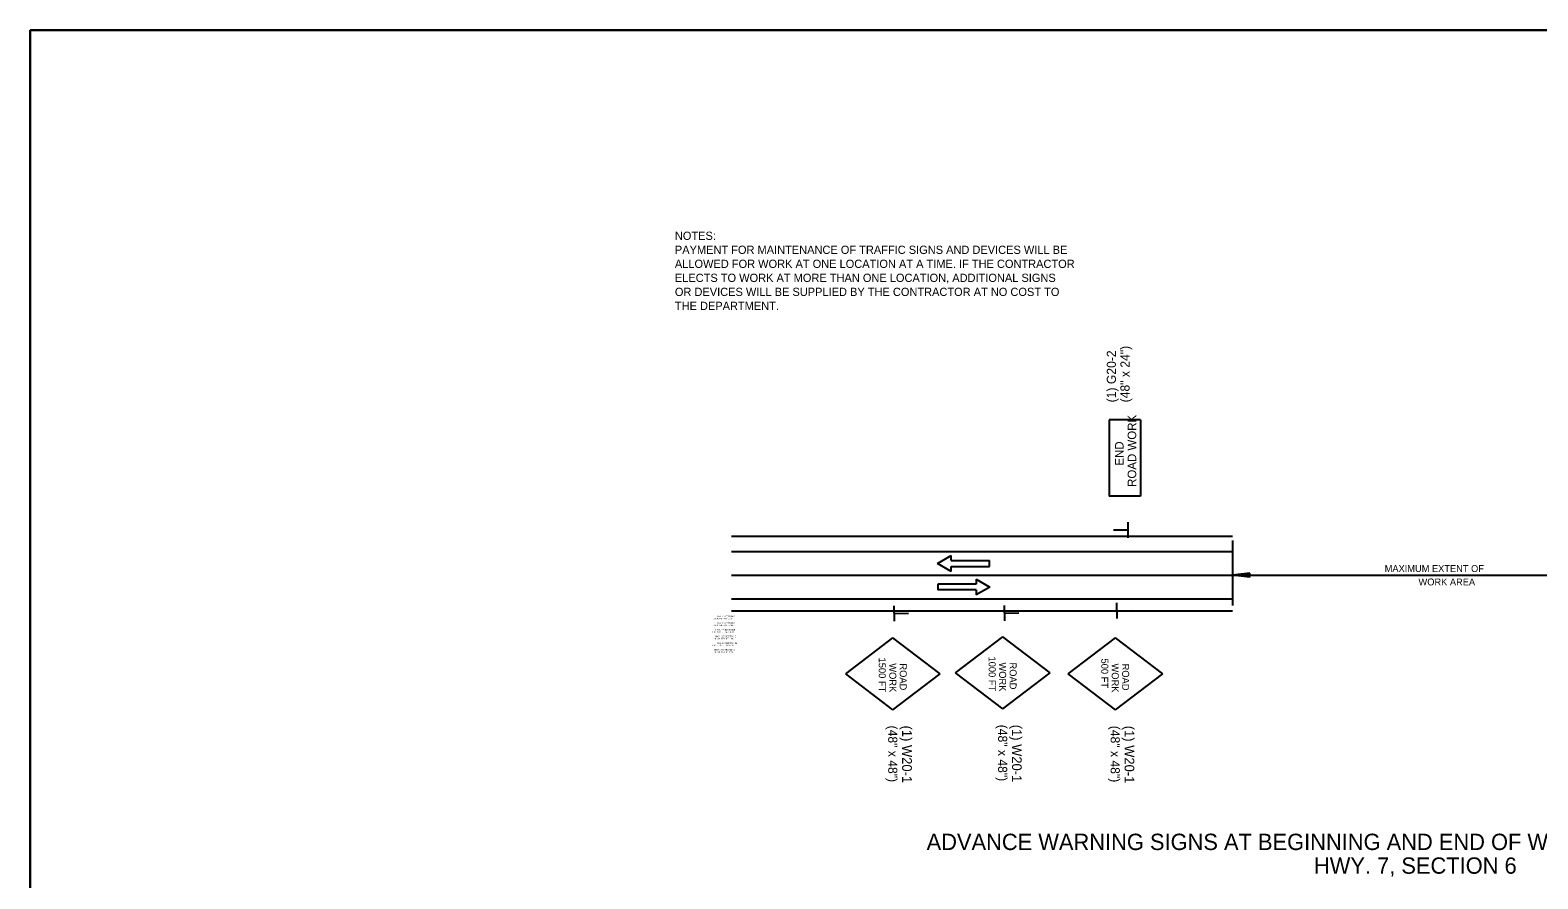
# Model space of a CAD drawing. Extents: x 1416408 to 1429341, y 372694 to 383211.
# Drawn here: x 1416408 to 1417967, y 376949 to 377826 of the extents above; entities that cross this region are included whole.
import ezdxf

# ---------------------------------------------------------------- set-up
doc = ezdxf.new("R2010")
doc.units = 0
for name, color, linetype in [('Default', 7, 'Continuous'), ('DSN_DRFT_Junk-No-Plot', 7, 'Continuous'), ('R_Border', 7, 'Continuous'), ('R_Draft', 7, 'Continuous'), ('R_Exist Surface', 7, 'Continuous'), ('R_MOT', 7, 'Continuous')]:
    doc.layers.add(name, color=color, linetype=linetype)

msp = doc.modelspace()

# ---------------------------------------------------------------- linework, layer by layer
at = {"layer": 'Default'}
for p, q in [((1417651, 377298.6), (1417651, 377231.7)), ((1417346, 377275), (1417359.9, 377283.1)), ((1417359.9, 377266.8), (1417346, 377275)), ((1417359.9, 377278), (1417359.9, 377283.1)), ((1417359.9, 377278), (1417399.5, 377278)), ((1417359.9, 377271.9), (1417399.5, 377271.9)), ((1417359.9, 377266.8), (1417359.9, 377271.9)), ((1417399.5, 377271.9), (1417399.5, 377278)), ((1417385.9, 377258.8), (1417385.9, 377253.7)), ((1417385.9, 377258.8), (1417399.8, 377250.6)), ((1417651, 377262.9), (1418113.3, 377262.9)), ((1417751.4, 377262.9), (1418012.8, 377262.9)), ((1417385.9, 377253.7), (1417346.3, 377253.7)), ((1417346.3, 377253.7), (1417346.3, 377247.6)), ((1417385.9, 377247.6), (1417346.3, 377247.6)), ((1417399.8, 377250.6), (1417385.9, 377242.5)), ((1417385.9, 377247.6), (1417385.9, 377242.5))]:
    msp.add_line(p, q, dxfattribs=at)
msp.add_lwpolyline([(1416407.7, 377826.5), (1416407.7, 376066.5), (1419127.7, 376066.5), (1419127.7, 377826.5)], close=True, dxfattribs=at)
at = {"layer": 'DSN_DRFT_Junk-No-Plot'}
msp.add_lwpolyline([(1416407.7, 377826.5), (1419127.7, 377826.5), (1419127.7, 376066.5), (1416407.7, 376066.5)], close=True, dxfattribs=at)
at = {"layer": 'R_Draft'}
for p, q in [((1417668.9, 377264.9), (1417651, 377262.9)), ((1417668.9, 377260.8), (1417651, 377262.9)), ((1417668.9, 377264.6), (1417654, 377262.9)), ((1417668.9, 377261.2), (1417654, 377262.9)), ((1417668.9, 377264.2), (1417657, 377262.9)), ((1417668.9, 377261.5), (1417657, 377262.9)), ((1417668.9, 377263.9), (1417660, 377262.9)), ((1417668.9, 377261.9), (1417660, 377262.9)), ((1417668.9, 377263.5), (1417663.1, 377262.9)), ((1417668.9, 377262.2), (1417663.1, 377262.9)), ((1417668.9, 377263.2), (1417666.1, 377262.9)), ((1417668.9, 377262.6), (1417666.1, 377262.9)), ((1417668.9, 377260.8), (1417668.9, 377264.9))]:
    msp.add_line(p, q, dxfattribs=at)
at = {"layer": 'R_Exist Surface'}
for p, q in [((1417133, 377303.1), (1417651, 377303.1)), ((1417133, 377287.4), (1417651, 377287.4)), ((1417133, 377262.9), (1417651, 377262.9)), ((1417133, 377238.3), (1417651, 377238.3)), ((1417133, 377226.1), (1417651, 377226.1))]:
    msp.add_line(p, q, dxfattribs=at)
at = {"layer": 'R_MOT'}
for p, q in [((1417523.2, 377423.6), (1417523.2, 377344.7)), ((1417555.9, 377423.6), (1417523.2, 377423.6)), ((1417555.9, 377423.6), (1417555.9, 377344.7)), ((1417555.9, 377344.7), (1417523.2, 377344.7)), ((1417542.5, 377317.6), (1417542.6, 377301.5)), ((1417542.2, 377309.6), (1417527.8, 377309.6)), ((1417301.3, 377215.3), (1417300.9, 377231.3)), ((1417415.5, 377215.7), (1417415.1, 377231.7)), ((1417415.6, 377223.7), (1417430, 377223.9)), ((1417531.5, 377218.2), (1417531.2, 377234.3)), ((1417531.6, 377226.2), (1417546.1, 377226.4)), ((1417301.4, 377223.3), (1417315.9, 377223.5)), ((1417250.9, 377160.9), (1417299.8, 377198.1)), ((1417348.7, 377160.9), (1417299.8, 377198.1)), ((1417364.6, 377161.9), (1417413.4, 377199.1)), ((1417462.4, 377161.9), (1417413.4, 377199.1)), ((1417481, 377160.8), (1417529.9, 377198)), ((1417578.8, 377160.8), (1417529.9, 377198)), ((1417413.4, 377124.7), (1417364.6, 377161.9)), ((1417413.4, 377124.7), (1417462.4, 377161.9)), ((1417299.8, 377123.7), (1417250.9, 377160.9)), ((1417299.8, 377123.7), (1417348.7, 377160.9)), ((1417529.9, 377123.6), (1417481, 377160.8)), ((1417529.9, 377123.6), (1417578.8, 377160.8))]:
    msp.add_line(p, q, dxfattribs=at)

# ---------------------------------------------------------------- texts
at = {"layer": 'Default'}
for s, height, p in [('NOTES: ', 8.52, (1417074.3, 377609.6)), ('PAYMENT FOR MAINTENANCE OF TRAFFIC SIGNS AND DEVICES WILL BE ', 8.521, (1417074.3, 377595.1)), ('ALLOWED FOR WORK AT ONE LOCATION AT A TIME. IF THE CONTRACTOR', 8.521, (1417074.3, 377580.6)), ('ELECTS TO WORK AT MORE THAN ONE LOCATION, ADDITIONAL SIGNS', 8.521, (1417074.3, 377566.1)), ('OR DEVICES WILL BE SUPPLIED BY THE CONTRACTOR AT NO COST TO ', 8.521, (1417074.3, 377551.6)), ('THE DEPARTMENT.', 8.521, (1417074.3, 377537.1)), ('MAXIMUM EXTENT OF ', 7.157, (1417808.2, 377266.2)), ('WORK AREA', 7.16, (1417843.2, 377252.3)), ('ADVANCE WARNING SIGNS AT BEGINNING AND END OF WORK ZONE', 16.891, (1417334.6, 376978.7)), ('HWY. 7, SECTION 6', 16.891, (1417735.1, 376954.2))]:
    msp.add_text(s, height=height, dxfattribs=at).set_placement(p)
at = {"layer": 'R_Border'}
for s, p in [('L.M. 6.353 - L.M. 6.972', (1417113.1, 377217.2)), ('L.M. 4.799 - L.M. 5.099', (1417113.1, 377210.3)), ('HWY. 7 SECTION 6', (1417117.2, 377219.5)), ('HWY. 7 SECTION 6', (1417117.2, 377212.6)), ('L.M. 4.620 - L.M. 4.890', (1417112.9, 377203.4)), ('L.M. 3.100 - L.M. 3.760', (1417113.4, 377196.5)), ('HWY. 128 SECTION 8', (1417116, 377198.8)), ('HWY. 67 SECTION 8', (1417116.3, 377205.7)), ('HWY. 15 SECTION 11', (1417117.2, 377191.9)), ('L.M. 3.527 - L.M. 3.728', (1417113.2, 377189.6)), ('L.M. 3.600 - L.M. 4.150', (1417113.4, 377182.7)), ('HWY. 376 SECTION 0', (1417115.3, 377185))]:
    msp.add_text(s, height=1.534, dxfattribs=at).set_placement(p)
at = {"layer": 'R_MOT'}
for s, height, rotation, p in [('(1) G20-2', 9.39, 90, (1417530.3, 377441.6)), ('(48" x 24")', 9.387, 90, (1417544.4, 377441.6)), ('ROAD WORK', 8.87, 90, (1417551.3, 377354.2)), ('END', 8.87, 90, (1417538.2, 377376.2)), ('1500 FT', 7.21, 270.0007, (1417285.1, 377177.7)), ('1000 FT', 7.21, 270.0007, (1417398.8, 377178.8)), ('WORK', 7.21, 270, (1417296, 377171.8)), ('ROAD', 7.21, 270.0006, (1417306.8, 377171.7)), ('WORK', 7.21, 270, (1417409.6, 377172.7)), ('ROAD', 7.21, 270.0006, (1417420.4, 377172.6)), (' 500 FT', 7.21, 270.0007, (1417515.2, 377179.4)), ('WORK', 7.21, 270, (1417526, 377171.6)), ('ROAD', 7.21, 270.0006, (1417536.8, 377171.5)), ('(48" x 48")', 9.387, 270, (1417294.9, 377107.4)), ('(1) W20-1', 10.01, 270, (1417309.3, 377107.4)), ('(48" x 48")', 9.387, 270, (1417408.5, 377108.3)), ('(1) W20-1', 10.01, 270, (1417422.9, 377108.3)), ('(48" x 48")', 9.387, 270, (1417524.9, 377107.2)), ('(1) W20-1', 10.01, 270, (1417539.3, 377107.2))]:
    msp.add_text(s, height=height, rotation=rotation, dxfattribs=at).set_placement(p)

doc.saveas('drawing.dxf')
